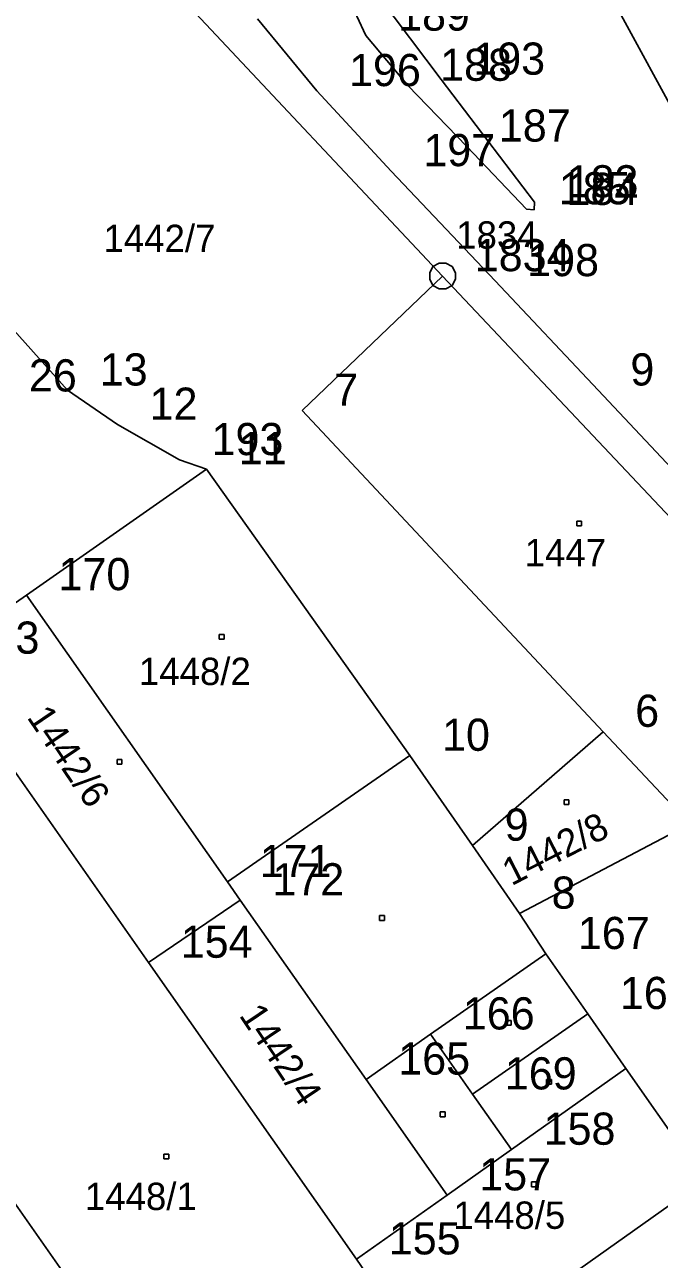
# Model space of a CAD drawing. Extents: x -822293 to -820259, y -1071573 to -1068794.
# Drawn here: x -821384 to -821344.6, y -1070417.6 to -1070340.8 of the extents above; entities that cross this region are included whole.
import ezdxf

# ---------------------------------------------------------------- set-up
doc = ezdxf.new("R2010")
doc.units = 0
for name, color, linetype in [('Vrstva 11', 7, 'Continuous'), ('Vrstva 14', 7, 'Continuous'), ('Vrstva 16', 7, 'Continuous'), ('Vrstva 2', 7, 'Continuous'), ('Vrstva 3', 7, 'Continuous'), ('Vrstva 6', 7, 'Continuous'), ('Vrstva 8', 7, 'Continuous'), ('Vrstva 9', 7, 'Continuous')]:
    doc.layers.add(name, color=color, linetype=linetype)

# ---------------------------------------------------------------- blocks, each defined once
blk = doc.blocks.new('Z402')
at = {"layer": 'Vrstva 2'}
for p, q in [((-10, 10), (20, 10)), ((-10, -20), (-10, 10)), ((20, 10), (20, -20)), ((20, -20), (-10, -20))]:
    blk.add_line(p, q, dxfattribs=at)
blk = doc.blocks.new('Z101')
at = {"layer": 'Vrstva 2'}
for p, q in [((-60, 60), (-20, 80)), ((-20, 80), (20, 80)), ((20, 80), (60, 60)), ((-80, 20), (-60, 60)), ((-80, -20), (-80, 20)), ((0, 0), (0, 0)), ((60, 60), (80, 20)), ((80, 20), (80, -20)), ((-60, -60), (-80, -20)), ((-20, -80), (-60, -60)), ((60, -60), (20, -80)), ((80, -20), (60, -60)), ((20, -80), (-20, -80))]:
    blk.add_line(p, q, dxfattribs=at)

msp = doc.modelspace()

# ---------------------------------------------------------------- linework, layer by layer
at = {"layer": 'Vrstva 2'}
for p, q in [((-821378.93, -1070334.19), (-821358.08, -1070356.41)), ((-821341.99, -1070349.38), (-821349.09, -1070336.3)), ((-821389.04, -1070354.95), (-821381.38, -1070363.52)), ((-821366.81, -1070364.78), (-821358.08, -1070356.41)), ((-821358.08, -1070356.41), (-821333.24, -1070382.81)), ((-821381.38, -1070363.52), (-821378.28, -1070365.65)), ((-821348.11, -1070384.75), (-821366.81, -1070364.78)), ((-821378.28, -1070365.65), (-821374.43, -1070367.85)), ((-821374.43, -1070367.85), (-821372.74, -1070368.42)), ((-821383.94, -1070376.25), (-821372.74, -1070368.42)), ((-821372.74, -1070368.42), (-821360.11, -1070386.24)), ((-821389.59, -1070380.2), (-821383.94, -1070376.25)), ((-821371.44, -1070394.09), (-821383.94, -1070376.25)), ((-821376.35, -1070399.11), (-821389.59, -1070380.2)), ((-821356.22, -1070391.83), (-821348.11, -1070384.75)), ((-821342.73, -1070390.49), (-821348.11, -1070384.75)), ((-821360.11, -1070386.24), (-821371.44, -1070394.09)), ((-821360.11, -1070386.24), (-821356.22, -1070391.83)), ((-821342.73, -1070390.49), (-821353.3, -1070396.06)), ((-821353.3, -1070396.06), (-821356.22, -1070391.83)), ((-821371.44, -1070394.09), (-821370.65, -1070395.23)), ((-821376.35, -1070399.11), (-821370.65, -1070395.23)), ((-821370.65, -1070395.23), (-821362.83, -1070406.38)), ((-821353.3, -1070396.06), (-821351.67, -1070398.57)), ((-821351.67, -1070398.57), (-821349.06, -1070402.3)), ((-821363.42, -1070417.56), (-821376.35, -1070399.11)), ((-821349.06, -1070402.3), (-821346.69, -1070405.7)), ((-821346.69, -1070405.7), (-821341.82, -1070412.67)), ((-821362.83, -1070406.38), (-821357.8, -1070413.58)), ((-821358.62, -1070424.58), (-821341.82, -1070412.67)), ((-821357.8, -1070413.58), (-821363.42, -1070417.56)), ((-821358.62, -1070424.58), (-821363.42, -1070417.56))]:
    msp.add_line(p, q, dxfattribs=at)
at = {"layer": 'Vrstva 3'}
for p, q in [((-821364.49, -1070337.88), (-821362.84, -1070341.45)), ((-821358.17, -1070344.19), (-821363.34, -1070337.32)), ((-821369.58, -1070340.42), (-821365.89, -1070344.9)), ((-821362.84, -1070341.45), (-821360.23, -1070344.57)), ((-821365.89, -1070344.9), (-821361.27, -1070349.88)), ((-821360.23, -1070344.57), (-821356.58, -1070348.35)), ((-821352.37, -1070351.82), (-821358.17, -1070344.19)), ((-821356.58, -1070348.35), (-821352.86, -1070352.25)), ((-821361.27, -1070349.88), (-821354.82, -1070356.72)), ((-821352.38, -1070352.29), (-821352.37, -1070351.82)), ((-821352.86, -1070352.25), (-821352.38, -1070352.29)), ((-821354.82, -1070356.72), (-821348.41, -1070363.52)), ((-821348.41, -1070363.52), (-821328.79, -1070384.4)), ((-821362.15, -1070446.14), (-821402.15, -1070389.16)), ((-821351.67, -1070398.57), (-821358.82, -1070403.57)), ((-821349.06, -1070402.3), (-821356.21, -1070407.3)), ((-821358.82, -1070403.57), (-821362.83, -1070406.38)), ((-821356.21, -1070407.3), (-821358.82, -1070403.57)), ((-821346.69, -1070405.7), (-821353.8, -1070410.74)), ((-821353.8, -1070410.74), (-821356.21, -1070407.3)), ((-821353.8, -1070410.74), (-821357.8, -1070413.58))]:
    msp.add_line(p, q, dxfattribs=at)
at = {"layer": 'Vrstva 8'}
for p, q in [((-821362.84, -1070341.45), (-821362.84, -1070341.45)), ((-821365.89, -1070344.9), (-821365.89, -1070344.9)), ((-821360.23, -1070344.57), (-821360.23, -1070344.57)), ((-821358.17, -1070344.19), (-821358.17, -1070344.19)), ((-821356.58, -1070348.35), (-821356.58, -1070348.35)), ((-821361.27, -1070349.88), (-821361.27, -1070349.88)), ((-821352.37, -1070351.82), (-821352.37, -1070351.82)), ((-821352.86, -1070352.25), (-821352.86, -1070352.25)), ((-821352.38, -1070352.29), (-821352.38, -1070352.29)), ((-821358.08, -1070356.41), (-821358.08, -1070356.41)), ((-821354.82, -1070356.72), (-821354.82, -1070356.72)), ((-821381.38, -1070363.52), (-821381.38, -1070363.52)), ((-821348.41, -1070363.52), (-821348.41, -1070363.52)), ((-821366.81, -1070364.78), (-821366.81, -1070364.78)), ((-821378.28, -1070365.65), (-821378.28, -1070365.65)), ((-821374.43, -1070367.85), (-821374.43, -1070367.85)), ((-821372.74, -1070368.42), (-821372.74, -1070368.42)), ((-821383.94, -1070376.25), (-821383.94, -1070376.25)), ((-821348.11, -1070384.75), (-821348.11, -1070384.75)), ((-821360.11, -1070386.24), (-821360.11, -1070386.24)), ((-821356.22, -1070391.83), (-821356.22, -1070391.83)), ((-821371.44, -1070394.09), (-821371.44, -1070394.09)), ((-821370.65, -1070395.23), (-821370.65, -1070395.23)), ((-821353.3, -1070396.06), (-821353.3, -1070396.06)), ((-821351.67, -1070398.57), (-821351.67, -1070398.57)), ((-821376.35, -1070399.11), (-821376.35, -1070399.11)), ((-821349.06, -1070402.3), (-821349.06, -1070402.3)), ((-821358.82, -1070403.57), (-821358.82, -1070403.57)), ((-821346.69, -1070405.7), (-821346.69, -1070405.7)), ((-821362.83, -1070406.38), (-821362.83, -1070406.38)), ((-821356.21, -1070407.3), (-821356.21, -1070407.3)), ((-821353.8, -1070410.74), (-821353.8, -1070410.74)), ((-821357.8, -1070413.58), (-821357.8, -1070413.58)), ((-821363.42, -1070417.56), (-821363.42, -1070417.56))]:
    msp.add_line(p, q, dxfattribs=at)

# ---------------------------------------------------------------- block references
at = {"layer": 'Vrstva 11', "xscale": 0.01, "yscale": 0.01}
for p in [(-821349.64, -1070371.75), (-821371.85, -1070378.8), (-821378.2, -1070386.58), (-821350.43, -1070389.08), (-821361.89, -1070396.29), (-821354.02, -1070402.81), (-821351.52, -1070406.48), (-821358.12, -1070408.5), (-821375.29, -1070411.12), (-821352.46, -1070412.85)]:
    msp.add_blockref('Z402', p, dxfattribs=at)
at = {"layer": 'Vrstva 14', "xscale": 0.01, "yscale": 0.01}
msp.add_blockref('Z101', (-821358.08, -1070356.41), dxfattribs=at)

# ---------------------------------------------------------------- texts
at = {"layer": 'Vrstva 16'}
msp.add_text('1834', height=1.7, dxfattribs=at).set_placement((-821357.232, -1070354.71))
at = {"layer": 'Vrstva 6'}
for s, p in [('1442/7', (-821379.146, -1070354.92)), ('1447', (-821352.976, -1070374.46)), ('1448/2', (-821376.946, -1070381.85)), ('1448/1', (-821380.303, -1070414.5)), ('1448/5', (-821357.408, -1070415.67))]:
    msp.add_text(s, height=1.7, dxfattribs=at).set_placement(p)
for s, rotation, p in [('1442/6', 304, (-821383.946, -1070383.852)), ('1442/8', 27, (-821353.799, -1070394.365)), ('1442/4', 304, (-821370.764, -1070402.395))]:
    msp.add_text(s, height=1.7, rotation=rotation, dxfattribs=at).set_placement(p)
at = {"layer": 'Vrstva 9'}
for s, p in [('189', (-821360.84, -1070341.15)), ('193', (-821356.17, -1070343.89)), ('196', (-821363.89, -1070344.6)), ('188', (-821358.23, -1070344.27)), ('187', (-821354.58, -1070348.05)), ('197', (-821359.27, -1070349.58)), ('183', (-821350.37, -1070351.52)), ('185', (-821350.86, -1070351.95)), ('184', (-821350.38, -1070351.99)), ('1834', (-821356.08, -1070356.11)), ('198', (-821352.82, -1070356.42)), ('26', (-821383.78, -1070363.59)), ('13', (-821379.38, -1070363.22)), ('9', (-821346.41, -1070363.22)), ('7', (-821364.81, -1070364.48)), ('12', (-821376.28, -1070365.35)), ('193', (-821372.43, -1070367.55)), ('11', (-821370.74, -1070368.12)), ('170', (-821381.94, -1070375.95)), ('153', (-821387.59, -1070379.9)), ('6', (-821346.11, -1070384.45)), ('10', (-821358.11, -1070385.94)), ('9', (-821354.22, -1070391.53)), ('171', (-821369.44, -1070393.79)), ('172', (-821368.65, -1070394.93)), ('8', (-821351.3, -1070395.76)), ('167', (-821349.67, -1070398.27)), ('154', (-821374.35, -1070398.81)), ('168', (-821347.06, -1070402)), ('166', (-821356.82, -1070403.27)), ('165', (-821360.83, -1070406.08)), ('169', (-821354.21, -1070407)), ('158', (-821351.8, -1070410.44)), ('157', (-821355.8, -1070413.28)), ('155', (-821361.42, -1070417.26))]:
    msp.add_text(s, height=2, dxfattribs=at).set_placement(p)

doc.saveas('drawing.dxf')
